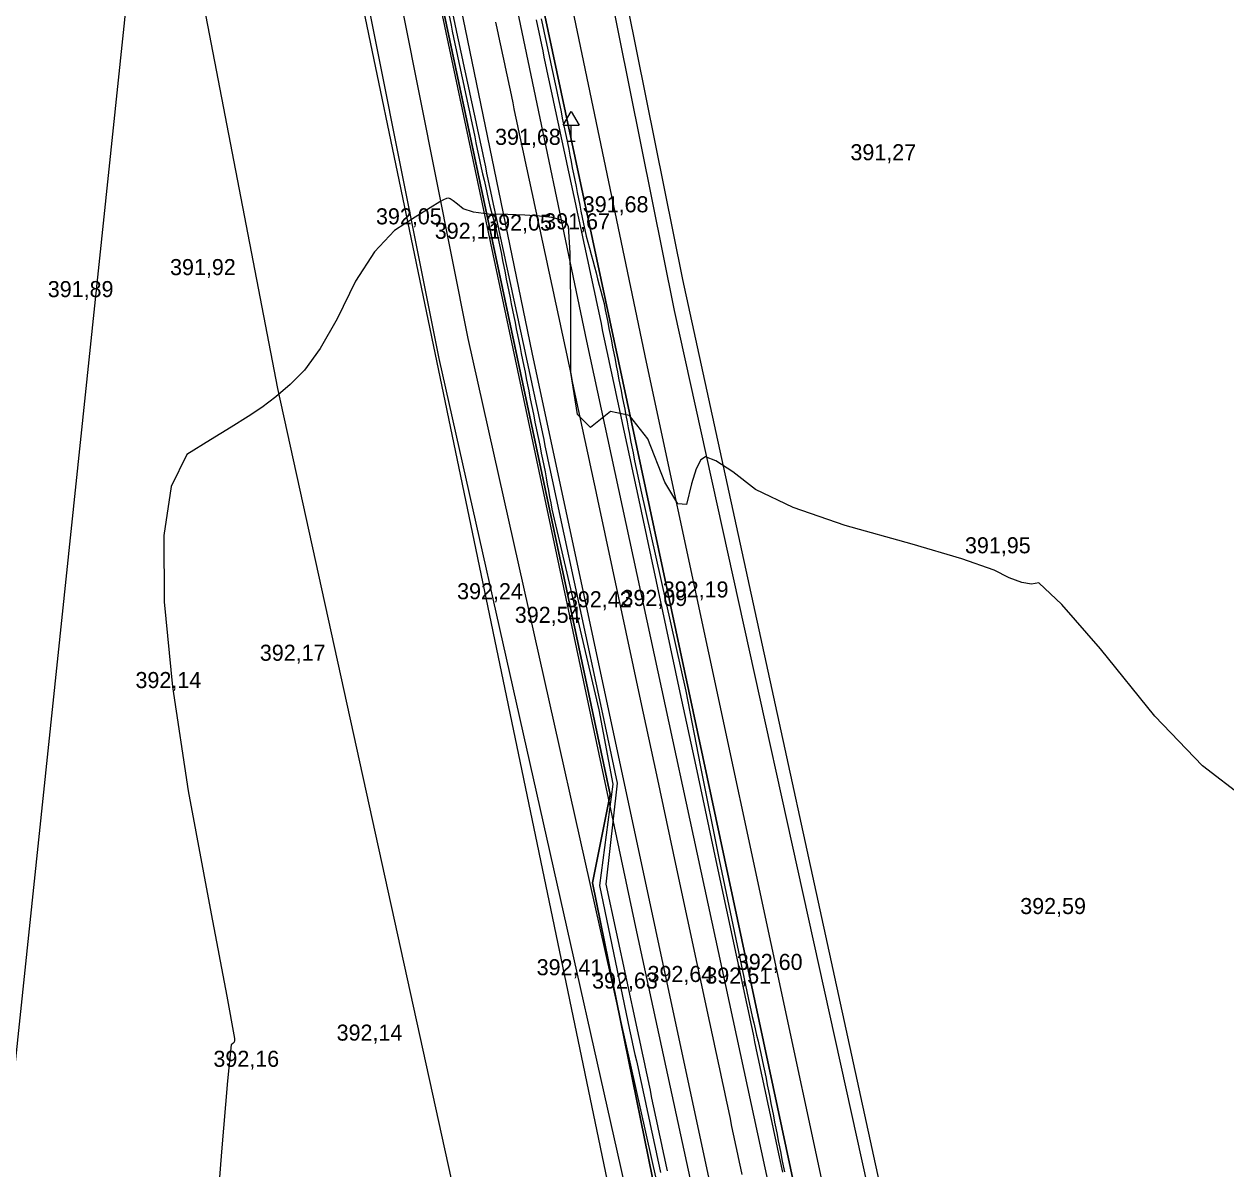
# Model space of a CAD drawing. Extents: x -574342 to -507939, y -1144044 to -1123894.
# Drawn here: x -508564.2 to -508489.4, y -1142959.6 to -1142888.4 of the extents above; entities that cross this region are included whole.
import ezdxf

# ---------------------------------------------------------------- set-up
doc = ezdxf.new("R2010")
doc.units = 0
for name, color, linetype in [('01_PARCELY_NAVRH_PC', 7, 'Continuous'), ('01_PARCELY_NAVRH_ŽP', 7, 'Continuous'), ('07_VODOVOD', 7, 'Continuous'), ('1000', 7, 'Continuous'), ('21', 7, 'Continuous'), ('37', 7, 'Continuous'), ('42', 7, 'Continuous'), ('52', 7, 'Continuous'), ('55', 7, 'Continuous'), ('Level 255', 7, 'Continuous'), ('VRST VEDL', 7, 'Continuous')]:
    doc.layers.add(name, color=color, linetype=linetype)

msp = doc.modelspace()

# ---------------------------------------------------------------- linework, layer by layer
at = {"layer": '01_PARCELY_NAVRH_PC'}
msp.add_lwpolyline([(-508546.584, -1142847.7), (-508527.76, -1142936.34), (-508528.85, -1142941.84), (-508524.62, -1142962.65), (-508521.23, -1142966.97), (-508506.03, -1143042.25), (-508499.26, -1143041.98), (-508503.94, -1143018.7), (-508540.355, -1142847.7)], dxfattribs=at)
at = {"layer": '01_PARCELY_NAVRH_ŽP'}
for points in [[(-508551.381, -1142847.7), (-508513, -1143032.18), (-508513.37, -1143051.16), (-508506.03, -1143042.25), (-508521.23, -1142966.97), (-508524.62, -1142962.65), (-508528.85, -1142941.84), (-508527.76, -1142936.34), (-508546.584, -1142847.7)], [(-508540.355, -1142847.7), (-508503.94, -1143018.7), (-508499.26, -1143041.98), (-508491.15, -1143065.29), (-508474.05, -1143124.14), (-508467.92, -1143139.18), (-508459.97, -1143152.33), (-508456.09, -1143158.71), (-508451.57, -1143168.14), (-508437.66, -1143207.58), (-508425.52, -1143241.92), (-508422.7, -1143249.88), (-508420.04, -1143252.1), (-508417.38, -1143252.95), (-508415.56, -1143252.78), (-508448.24, -1143160.16), (-508453.75, -1143145.01), (-508465.11, -1143123.03), (-508471.48, -1143106.99), (-508484.55, -1143061.98), (-508495.62, -1143031.06), (-508523.23, -1142904.28), (-508534.61, -1142847.7)]]:
    msp.add_lwpolyline(points, dxfattribs=at)
at = {"layer": '07_VODOVOD'}
for points in [[(-508656.802, -1143831.742), (-508553.726, -1142847.7)], [(-508640.05, -1143130.18), (-508637.48, -1143128.83), (-508626.48, -1143135.95), (-508617.09, -1143140.73), (-508602.61, -1143146.08), (-508586.87, -1143149.65), (-508578.03, -1143148.66), (-508571.02, -1143145.86), (-508562.51, -1143139.92), (-508546.01, -1143124.95), (-508535.68, -1143117.17), (-508526.75, -1143109.24), (-508521.13, -1143103.37), (-508515.47, -1143095.19), (-508511.95, -1143085.3), (-508511.14, -1143074.49), (-508510.31, -1143059.6), (-508507.36, -1143039.1), (-508508.06, -1143029.96), (-508510.42, -1143015.75), (-508519.77, -1142974.08), (-508526.08, -1142944.88), (-508540.82, -1142875.36), (-508546.434, -1142847.7)]]:
    msp.add_lwpolyline(points, dxfattribs=at)
at = {"layer": '1000'}
for points in [[(-508538.971, -1142882.183), (-508537.655, -1142888.435), (-508537.575, -1142888.822), (-508537.493, -1142889.208), (-508537.412, -1142889.594), (-508537.331, -1142889.98), (-508537.25, -1142890.366), (-508537.168, -1142890.753), (-508537.087, -1142891.139), (-508537.005, -1142891.525), (-508536.923, -1142891.911), (-508536.842, -1142892.297), (-508536.76, -1142892.683), (-508536.678, -1142893.069), (-508536.595, -1142893.455), (-508536.513, -1142893.841), (-508536.431, -1142894.227), (-508536.349, -1142894.613), (-508536.266, -1142894.999), (-508536.183, -1142895.385), (-508536.101, -1142895.77), (-508536.018, -1142896.156), (-508535.935, -1142896.542), (-508535.852, -1142896.928), (-508535.769, -1142897.314), (-508535.686, -1142897.699), (-508535.602, -1142898.085), (-508535.519, -1142898.471), (-508535.435, -1142898.857), (-508535.352, -1142899.242), (-508535.257, -1142899.626), (-508535.156, -1142900.008), (-508535.056, -1142900.39), (-508534.955, -1142900.772), (-508534.855, -1142901.154), (-508534.755, -1142901.536), (-508534.678, -1142901.923), (-508534.601, -1142902.31), (-508534.524, -1142902.697), (-508534.447, -1142903.084), (-508534.369, -1142903.471), (-508534.292, -1142903.858), (-508534.215, -1142904.245), (-508534.137, -1142904.632), (-508534.059, -1142905.019), (-508533.982, -1142905.406), (-508533.904, -1142905.793), (-508533.826, -1142906.18), (-508533.748, -1142906.567), (-508533.669, -1142906.954), (-508533.591, -1142907.34), (-508533.513, -1142907.727), (-508533.436, -1142908.114), (-508533.359, -1142908.501), (-508533.282, -1142908.889), (-508533.205, -1142909.276), (-508533.128, -1142909.663), (-508533.05, -1142910.05), (-508532.973, -1142910.437), (-508532.896, -1142910.824), (-508532.818, -1142911.211), (-508532.74, -1142911.598), (-508532.662, -1142911.984), (-508532.585, -1142912.371), (-508532.507, -1142912.758), (-508532.429, -1142913.145), (-508532.35, -1142913.532), (-508532.272, -1142913.919), (-508532.194, -1142914.306), (-508532.115, -1142914.692), (-508532.037, -1142915.079), (-508531.958, -1142915.466), (-508531.879, -1142915.853), (-508531.805, -1142916.24), (-508531.735, -1142916.629), (-508531.664, -1142917.017), (-508531.594, -1142917.406), (-508531.523, -1142917.794), (-508531.452, -1142918.182), (-508531.381, -1142918.571), (-508528.464, -1142931.067), (-508527.581, -1142935.684), (-508528.416, -1142941.999), (-508526.544, -1142950.984), (-508526.459, -1142951.37), (-508526.374, -1142951.756), (-508526.289, -1142952.142), (-508526.205, -1142952.528), (-508526.12, -1142952.914), (-508526.036, -1142953.3), (-508525.952, -1142953.686), (-508525.868, -1142954.072), (-508525.784, -1142954.458), (-508525.7, -1142954.844), (-508525.616, -1142955.231), (-508525.532, -1142955.617), (-508525.449, -1142956.003), (-508525.365, -1142956.389), (-508525.282, -1142956.775), (-508525.199, -1142957.162), (-508525.116, -1142957.548), (-508525.033, -1142957.934), (-508524.95, -1142958.32), (-508524.867, -1142958.707), (-508524.784, -1142959.093), (-508524.702, -1142959.48), (-508524.619, -1142959.866)], [(-508538.755, -1142882.137), (-508537.419, -1142888.385), (-508537.336, -1142888.771), (-508537.253, -1142889.157), (-508537.171, -1142889.542), (-508537.088, -1142889.928), (-508537.006, -1142890.314), (-508536.923, -1142890.7), (-508536.841, -1142891.086), (-508536.758, -1142891.472), (-508536.676, -1142891.858), (-508536.593, -1142892.244), (-508536.511, -1142892.63), (-508536.428, -1142893.016), (-508536.346, -1142893.402), (-508536.263, -1142893.787), (-508536.181, -1142894.173), (-508536.098, -1142894.559), (-508536.016, -1142894.945), (-508535.933, -1142895.331), (-508535.85, -1142895.717), (-508535.768, -1142896.103), (-508535.685, -1142896.489), (-508535.603, -1142896.875), (-508535.52, -1142897.261), (-508535.438, -1142897.646), (-508535.355, -1142898.032), (-508535.273, -1142898.418), (-508535.19, -1142898.804), (-508535.108, -1142899.19), (-508535.025, -1142899.576), (-508534.943, -1142899.962), (-508534.86, -1142900.348), (-508534.778, -1142900.734), (-508534.695, -1142901.12), (-508534.613, -1142901.506), (-508534.53, -1142901.891), (-508534.447, -1142902.277), (-508534.365, -1142902.663), (-508534.282, -1142903.049), (-508534.2, -1142903.435), (-508534.117, -1142903.821), (-508534.035, -1142904.207), (-508533.952, -1142904.593), (-508533.87, -1142904.979), (-508533.787, -1142905.365), (-508533.705, -1142905.75), (-508533.622, -1142906.136), (-508533.54, -1142906.522), (-508533.457, -1142906.908), (-508533.375, -1142907.294), (-508533.292, -1142907.68), (-508533.21, -1142908.066), (-508533.127, -1142908.452), (-508533.044, -1142908.838), (-508532.962, -1142909.224), (-508532.879, -1142909.61), (-508532.797, -1142909.995), (-508532.714, -1142910.381), (-508532.632, -1142910.767), (-508532.549, -1142911.153), (-508532.467, -1142911.539), (-508532.384, -1142911.925), (-508532.302, -1142912.311), (-508532.219, -1142912.697), (-508532.137, -1142913.083), (-508532.054, -1142913.469), (-508531.972, -1142913.854), (-508531.889, -1142914.24), (-508531.807, -1142914.626), (-508531.724, -1142915.012), (-508531.641, -1142915.398), (-508531.559, -1142915.784), (-508531.476, -1142916.17), (-508531.394, -1142916.556), (-508531.311, -1142916.942), (-508531.229, -1142917.328), (-508531.146, -1142917.714), (-508531.064, -1142918.099), (-508530.981, -1142918.485), (-508528.298, -1142931.031), (-508527.315, -1142935.627), (-508528.016, -1142941.913), (-508526.097, -1142950.889), (-508526.014, -1142951.275), (-508525.931, -1142951.661), (-508525.849, -1142952.048), (-508525.766, -1142952.434), (-508525.684, -1142952.821), (-508525.601, -1142953.207), (-508525.518, -1142953.593), (-508525.436, -1142953.98), (-508525.353, -1142954.366), (-508525.27, -1142954.753), (-508525.188, -1142955.139), (-508525.105, -1142955.525), (-508525.022, -1142955.912), (-508524.94, -1142956.298), (-508524.857, -1142956.684), (-508524.775, -1142957.071), (-508524.692, -1142957.457), (-508524.609, -1142957.844), (-508524.527, -1142958.23), (-508524.444, -1142958.616), (-508524.361, -1142959.003), (-508524.279, -1142959.389), (-508524.196, -1142959.775)], [(-508532.364, -1142888.111), (-508532.282, -1142888.497), (-508532.199, -1142888.883), (-508532.116, -1142889.269), (-508532.034, -1142889.655), (-508531.951, -1142890.04), (-508531.869, -1142890.426), (-508531.786, -1142890.812), (-508531.704, -1142891.198), (-508531.621, -1142891.584), (-508531.539, -1142891.97), (-508531.456, -1142892.356), (-508531.374, -1142892.742), (-508531.291, -1142893.128), (-508531.209, -1142893.514), (-508531.126, -1142893.899), (-508531.044, -1142894.285), (-508530.961, -1142894.671), (-508530.879, -1142895.057), (-508530.796, -1142895.443), (-508530.713, -1142895.829), (-508530.631, -1142896.215), (-508530.548, -1142896.601), (-508530.466, -1142896.987), (-508530.383, -1142897.373), (-508530.301, -1142897.759), (-508530.218, -1142898.144), (-508530.136, -1142898.53), (-508530.053, -1142898.916), (-508529.971, -1142899.302), (-508529.888, -1142899.688), (-508529.806, -1142900.074), (-508529.723, -1142900.46), (-508529.641, -1142900.846), (-508529.558, -1142901.232), (-508529.476, -1142901.618), (-508529.393, -1142902.003), (-508529.31, -1142902.389), (-508529.228, -1142902.775), (-508529.145, -1142903.161), (-508529.063, -1142903.547), (-508528.98, -1142903.933), (-508528.898, -1142904.319), (-508528.815, -1142904.705), (-508528.733, -1142905.091), (-508528.65, -1142905.477), (-508528.568, -1142905.863), (-508528.485, -1142906.248), (-508528.403, -1142906.634), (-508528.32, -1142907.02), (-508528.238, -1142907.406), (-508528.155, -1142907.792), (-508528.073, -1142908.178), (-508527.99, -1142908.564), (-508527.907, -1142908.95), (-508527.825, -1142909.336), (-508527.742, -1142909.722), (-508527.66, -1142910.108), (-508527.577, -1142910.493), (-508527.495, -1142910.879), (-508527.412, -1142911.265), (-508527.33, -1142911.651), (-508527.247, -1142912.037), (-508527.165, -1142912.423), (-508527.082, -1142912.809), (-508527, -1142913.195), (-508526.917, -1142913.581), (-508526.835, -1142913.967), (-508526.752, -1142914.352), (-508526.669, -1142914.738), (-508526.587, -1142915.124), (-508526.504, -1142915.51), (-508526.422, -1142915.896), (-508526.339, -1142916.282), (-508526.257, -1142916.668), (-508526.174, -1142917.054), (-508526.092, -1142917.44), (-508523.409, -1142929.986), (-508522.426, -1142934.582), (-508521.171, -1142940.449), (-508519.251, -1142949.425), (-508519.169, -1142949.811), (-508519.086, -1142950.198), (-508519.004, -1142950.584), (-508518.921, -1142950.97), (-508518.838, -1142951.357), (-508518.756, -1142951.743), (-508518.673, -1142952.129), (-508518.59, -1142952.516), (-508518.508, -1142952.902), (-508518.425, -1142953.289), (-508518.343, -1142953.675), (-508518.26, -1142954.061), (-508518.177, -1142954.448), (-508518.095, -1142954.834), (-508518.012, -1142955.221), (-508517.929, -1142955.607), (-508517.847, -1142955.993), (-508517.764, -1142956.38), (-508517.681, -1142956.766), (-508517.599, -1142957.152), (-508517.516, -1142957.539), (-508517.434, -1142957.925), (-508517.351, -1142958.312), (-508517.268, -1142958.698), (-508517.186, -1142959.084), (-508517.103, -1142959.471), (-508517.02, -1142959.857)], [(-508532.04, -1142888.042), (-508531.957, -1142888.427), (-508531.875, -1142888.813), (-508531.792, -1142889.199), (-508531.71, -1142889.585), (-508531.627, -1142889.971), (-508531.545, -1142890.357), (-508531.463, -1142890.743), (-508531.381, -1142891.129), (-508531.299, -1142891.515), (-508531.217, -1142891.901), (-508531.135, -1142892.287), (-508531.054, -1142892.673), (-508530.972, -1142893.059), (-508530.891, -1142893.446), (-508530.81, -1142893.832), (-508530.728, -1142894.218), (-508530.647, -1142894.604), (-508530.566, -1142894.99), (-508530.484, -1142895.376), (-508530.402, -1142895.762), (-508530.325, -1142896.15), (-508530.258, -1142896.539), (-508530.187, -1142896.927), (-508530.109, -1142897.314), (-508530.031, -1142897.701), (-508529.954, -1142898.088), (-508529.876, -1142898.475), (-508529.799, -1142898.862), (-508529.722, -1142899.249), (-508529.645, -1142899.636), (-508529.567, -1142900.023), (-508529.491, -1142900.41), (-508529.414, -1142900.797), (-508529.337, -1142901.184), (-508529.237, -1142901.567), (-508529.135, -1142901.948), (-508529.034, -1142902.33), (-508528.933, -1142902.712), (-508528.832, -1142903.094), (-508528.731, -1142903.476), (-508528.63, -1142903.858), (-508528.53, -1142904.24), (-508528.429, -1142904.622), (-508528.329, -1142905.004), (-508528.229, -1142905.386), (-508528.132, -1142905.769), (-508528.056, -1142906.157), (-508527.979, -1142906.544), (-508527.903, -1142906.931), (-508527.827, -1142907.318), (-508527.751, -1142907.706), (-508527.675, -1142908.093), (-508527.599, -1142908.48), (-508527.523, -1142908.868), (-508527.448, -1142909.255), (-508527.372, -1142909.642), (-508527.297, -1142910.03), (-508527.222, -1142910.417), (-508527.146, -1142910.805), (-508527.071, -1142911.192), (-508526.996, -1142911.58), (-508526.921, -1142911.967), (-508526.847, -1142912.355), (-508526.772, -1142912.742), (-508526.697, -1142913.13), (-508526.623, -1142913.518), (-508526.548, -1142913.905), (-508526.474, -1142914.293), (-508526.4, -1142914.681), (-508526.326, -1142915.068), (-508526.252, -1142915.456), (-508526.172, -1142915.843), (-508526.091, -1142916.229), (-508526.011, -1142916.615), (-508525.93, -1142917.002), (-508525.85, -1142917.388), (-508523.047, -1142929.908), (-508522.138, -1142934.52), (-508520.971, -1142940.406), (-508519.079, -1142949.388), (-508518.99, -1142949.773), (-508518.902, -1142950.158), (-508518.813, -1142950.543), (-508518.725, -1142950.928), (-508518.636, -1142951.313), (-508518.547, -1142951.698), (-508518.458, -1142952.083), (-508518.369, -1142952.468), (-508518.28, -1142952.853), (-508518.196, -1142953.24), (-508518.121, -1142953.628), (-508518.046, -1142954.016), (-508517.97, -1142954.404), (-508517.895, -1142954.791), (-508517.82, -1142955.179), (-508517.744, -1142955.567), (-508517.668, -1142955.955), (-508517.593, -1142956.343), (-508517.517, -1142956.731), (-508517.441, -1142957.119), (-508517.365, -1142957.506), (-508517.289, -1142957.894), (-508517.212, -1142958.282), (-508517.136, -1142958.67), (-508517.06, -1142959.057), (-508516.983, -1142959.445), (-508516.907, -1142959.833)]]:
    msp.add_lwpolyline(points, dxfattribs=at)
at = {"layer": '21'}
msp.add_lwpolyline([(-508534.891, -1142888.248), (-508534.809, -1142888.634), (-508534.726, -1142889.02), (-508534.644, -1142889.406), (-508534.561, -1142889.791), (-508534.479, -1142890.177), (-508534.396, -1142890.563), (-508534.314, -1142890.949), (-508534.231, -1142891.335), (-508534.149, -1142891.721), (-508534.066, -1142892.107), (-508533.983, -1142892.493), (-508533.901, -1142892.879), (-508533.818, -1142893.265), (-508533.736, -1142893.651), (-508533.653, -1142894.036), (-508533.571, -1142894.422), (-508533.488, -1142894.808), (-508533.406, -1142895.194), (-508533.323, -1142895.58), (-508533.241, -1142895.966), (-508533.158, -1142896.352), (-508533.076, -1142896.738), (-508532.993, -1142897.124), (-508532.911, -1142897.51), (-508532.828, -1142897.895), (-508532.746, -1142898.281), (-508532.663, -1142898.667), (-508532.58, -1142899.053), (-508532.498, -1142899.439), (-508532.415, -1142899.825), (-508532.333, -1142900.211), (-508532.25, -1142900.597), (-508532.168, -1142900.983), (-508532.085, -1142901.369), (-508532.003, -1142901.755), (-508531.92, -1142902.14), (-508531.838, -1142902.526), (-508531.755, -1142902.912), (-508531.673, -1142903.298), (-508531.59, -1142903.684), (-508531.508, -1142904.07), (-508531.425, -1142904.456), (-508531.343, -1142904.842), (-508531.26, -1142905.228), (-508531.177, -1142905.614), (-508531.095, -1142905.999), (-508531.012, -1142906.385), (-508530.93, -1142906.771), (-508530.847, -1142907.157), (-508530.765, -1142907.543), (-508530.682, -1142907.929), (-508530.6, -1142908.315), (-508530.517, -1142908.701), (-508530.435, -1142909.087), (-508530.352, -1142909.473), (-508530.27, -1142909.859), (-508530.187, -1142910.244), (-508530.105, -1142910.63), (-508530.022, -1142911.016), (-508529.94, -1142911.402), (-508529.857, -1142911.788), (-508529.774, -1142912.174), (-508529.692, -1142912.56), (-508529.609, -1142912.946), (-508529.527, -1142913.332), (-508529.444, -1142913.718), (-508529.362, -1142914.103), (-508529.279, -1142914.489), (-508529.197, -1142914.875), (-508529.114, -1142915.261), (-508529.032, -1142915.647), (-508528.949, -1142916.033), (-508528.867, -1142916.419), (-508528.784, -1142916.805), (-508528.702, -1142917.191), (-508528.619, -1142917.577), (-508528.537, -1142917.963), (-508525.853, -1142930.508), (-508524.871, -1142935.105), (-508523.616, -1142940.972), (-508521.696, -1142949.948), (-508521.614, -1142950.334), (-508521.531, -1142950.72), (-508521.448, -1142951.107), (-508521.366, -1142951.493), (-508521.283, -1142951.88), (-508521.2, -1142952.266), (-508521.118, -1142952.652), (-508521.035, -1142953.039), (-508520.952, -1142953.425), (-508520.87, -1142953.811), (-508520.787, -1142954.198), (-508520.705, -1142954.584), (-508520.622, -1142954.971), (-508520.539, -1142955.357), (-508520.457, -1142955.743), (-508520.374, -1142956.13), (-508520.291, -1142956.516), (-508520.209, -1142956.902), (-508520.126, -1142957.289), (-508520.044, -1142957.675), (-508519.961, -1142958.062), (-508519.878, -1142958.448), (-508519.796, -1142958.834), (-508519.713, -1142959.221), (-508519.63, -1142959.607), (-508519.548, -1142959.994)], dxfattribs=at)
at = {"layer": '37'}
for points in [[(-508511.59, -1143124.92), (-508509.54, -1143119.35), (-508506.51, -1143105.44), (-508506, -1143084.25), (-508505.31, -1143056.58), (-508505.39, -1143050.71), (-508505.49, -1143042.55), (-508509.4, -1143015.37), (-508521.08, -1142962.59), (-508532.6, -1142908.81), (-508545.204, -1142847.7)], [(-508511.59, -1143124.92), (-508509.54, -1143119.35), (-508506.51, -1143105.44), (-508506, -1143084.25), (-508505.31, -1143056.58), (-508505.39, -1143050.71), (-508505.49, -1143042.55), (-508509.4, -1143015.37), (-508521.08, -1142962.59), (-508532.6, -1142908.81), (-508545.204, -1142847.7)], [(-508541.866, -1142847.7), (-508529.22, -1142908.11), (-508517.67, -1142961.7), (-508506.14, -1143014.46), (-508500.54, -1143041.74), (-508495.34, -1143058.46)], [(-508541.866, -1142847.7), (-508529.22, -1142908.11), (-508517.67, -1142961.7), (-508506.14, -1143014.46), (-508500.54, -1143041.74), (-508495.34, -1143058.46)]]:
    msp.add_lwpolyline(points, dxfattribs=at)
at = {"layer": '42'}
for points in [[(-508560.651, -1142847.7), (-508548.46, -1142911.06), (-508536.86, -1142963.87), (-508529.29, -1143000.8), (-508523.32, -1143047.2)], [(-508560.651, -1142847.7), (-508548.46, -1142911.06), (-508536.86, -1142963.87), (-508529.29, -1143000.8), (-508523.32, -1143047.2)], [(-508510.77, -1143053.59), (-508510.65, -1143044.07), (-508514.85, -1143017.75), (-508526.24, -1142963.32), (-508538.39, -1142909.19), (-508550.685, -1142847.7)], [(-508510.77, -1143053.59), (-508510.65, -1143044.07), (-508514.85, -1143017.75), (-508526.24, -1142963.32), (-508538.39, -1142909.19), (-508550.685, -1142847.7)], [(-508445.89, -1143059.01), (-508479.63, -1143062.18), (-508484.42, -1143059.76), (-508487.39, -1143055.01), (-508499.96, -1143010.2), (-508511.4, -1142962.16), (-508523.74, -1142906.21), (-508535.517, -1142847.7)], [(-508445.89, -1143059.01), (-508479.63, -1143062.18), (-508484.42, -1143059.76), (-508487.39, -1143055.01), (-508499.96, -1143010.2), (-508511.4, -1142962.16), (-508523.74, -1142906.21), (-508535.517, -1142847.7)]]:
    msp.add_lwpolyline(points, dxfattribs=at)
at = {"layer": '52'}
for p, q in [((-508530.67, -1142894.66), (-508530.17, -1142893.81)), ((-508530.17, -1142893.81), (-508529.67, -1142894.66)), ((-508530.67, -1142894.66), (-508529.67, -1142894.66)), ((-508530.17, -1142895.66), (-508530.17, -1142894.66)), ((-508530.42, -1142895.66), (-508529.92, -1142895.66))]:
    msp.add_line(p, q, dxfattribs=at)
at = {"layer": '55'}
for points in [[(-508548.593, -1142847.7), (-508536.61, -1142907.95), (-508524.27, -1142963.1), (-508513.79, -1143010.01), (-508509.84, -1143035.05), (-508508.31, -1143060.76)], [(-508548.593, -1142847.7), (-508536.61, -1142907.95), (-508524.27, -1142963.1), (-508513.79, -1143010.01), (-508509.84, -1143035.05), (-508508.31, -1143060.76)], [(-508492.58, -1143052.86), (-508498.99, -1143029.87), (-508513.85, -1142963.71), (-508525.48, -1142909.41), (-508538.364, -1142847.7)], [(-508492.58, -1143052.86), (-508498.99, -1143029.87), (-508513.85, -1142963.71), (-508525.48, -1142909.41), (-508538.364, -1142847.7)]]:
    msp.add_lwpolyline(points, dxfattribs=at)
at = {"layer": 'VRST VEDL'}
msp.add_lwpolyline([(-508488.286, -1142936.545), (-508490.871, -1142934.552), (-508493.854, -1142931.46), (-508497.232, -1142927.267), (-508499.636, -1142924.499), (-508501.065, -1142923.155), (-508501.519, -1142923.235), (-508502.135, -1142923.131), (-508502.914, -1142922.841), (-508503.857, -1142922.367), (-508505.871, -1142921.668), (-508508.958, -1142920.745), (-508513.118, -1142919.597), (-508516.365, -1142918.463), (-508518.7, -1142917.344), (-508520.123, -1142916.24), (-508521.165, -1142915.566), (-508521.826, -1142915.323), (-508522.106, -1142915.509), (-508522.394, -1142916.064), (-508522.688, -1142916.989), (-508522.989, -1142918.282), (-508523.544, -1142918.247), (-508524.352, -1142916.884), (-508525.414, -1142914.194), (-508526.537, -1142912.731), (-508527.72, -1142912.497), (-508528.964, -1142913.49), (-508529.793, -1142912.678), (-508530.207, -1142910.062), (-508530.206, -1142905.641), (-508530.25, -1142902.614), (-508530.339, -1142900.982), (-508530.472, -1142900.745), (-508530.818, -1142900.558), (-508531.377, -1142900.42), (-508532.149, -1142900.332), (-508533.065, -1142900.265), (-508534.127, -1142900.219), (-508535.333, -1142900.195), (-508536.257, -1142900.081), (-508536.9, -1142899.875), (-508537.262, -1142899.58), (-508537.531, -1142899.371), (-508537.709, -1142899.25), (-508537.793, -1142899.216), (-508537.93, -1142899.236), (-508538.117, -1142899.311), (-508538.356, -1142899.44), (-508538.946, -1142899.802), (-508539.887, -1142900.398), (-508541.179, -1142901.227), (-508542.42, -1142902.556), (-508543.611, -1142904.385), (-508544.752, -1142906.715), (-508545.81, -1142908.562), (-508546.785, -1142909.924), (-508547.678, -1142910.804), (-508548.559, -1142911.575), (-508549.428, -1142912.238), (-508550.285, -1142912.794), (-508551.348, -1142913.467), (-508552.617, -1142914.259), (-508554.092, -1142915.169), (-508555.065, -1142917.151), (-508555.536, -1142920.205), (-508555.504, -1142924.331), (-508555.001, -1142929.632), (-508554.025, -1142936.108), (-508552.578, -1142943.759), (-508551.612, -1142948.901), (-508551.127, -1142951.533), (-508551.124, -1142951.656), (-508551.157, -1142951.76), (-508551.227, -1142951.846), (-508551.334, -1142951.914), (-508551.575, -1142954.161), (-508551.951, -1142958.587), (-508552.973, -1142971.797)], dxfattribs=at)

# ---------------------------------------------------------------- texts
at = {"layer": 'Level 255'}
for s, p in [('391,68', (-508534.915, -1142895.89)), ('391,27', (-508512.795, -1142896.85)), ('391,68', (-508529.455, -1142900.09)), ('392,05', (-508542.325, -1142900.84)), ('392,05', (-508535.465, -1142901.23)), ('391,67', (-508531.855, -1142901.15)), ('392,11', (-508538.665, -1142901.74)), ('391,92', (-508555.145, -1142904)), ('391,89', (-508562.755, -1142905.37)), ('391,95', (-508505.665, -1142921.32)), ('392,24', (-508537.275, -1142924.18)), ('392,19', (-508524.475, -1142924.07)), ('392,42', (-508530.505, -1142924.68)), ('392,09', (-508527.045, -1142924.6)), ('392,54', (-508533.685, -1142925.65)), ('392,17', (-508549.555, -1142928.01)), ('392,14', (-508557.295, -1142929.71)), ('392,59', (-508502.225, -1142943.78)), ('392,41', (-508532.325, -1142947.59)), ('392,60', (-508519.865, -1142947.26)), ('392,63', (-508528.875, -1142948.42)), ('392,64', (-508525.425, -1142948.01)), ('392,51', (-508521.825, -1142948.11)), ('392,14', (-508544.775, -1142951.66)), ('392,16', (-508552.445, -1142953.29))]:
    msp.add_text(s, height=1, dxfattribs=at).set_placement(p)

doc.saveas('drawing.dxf')
